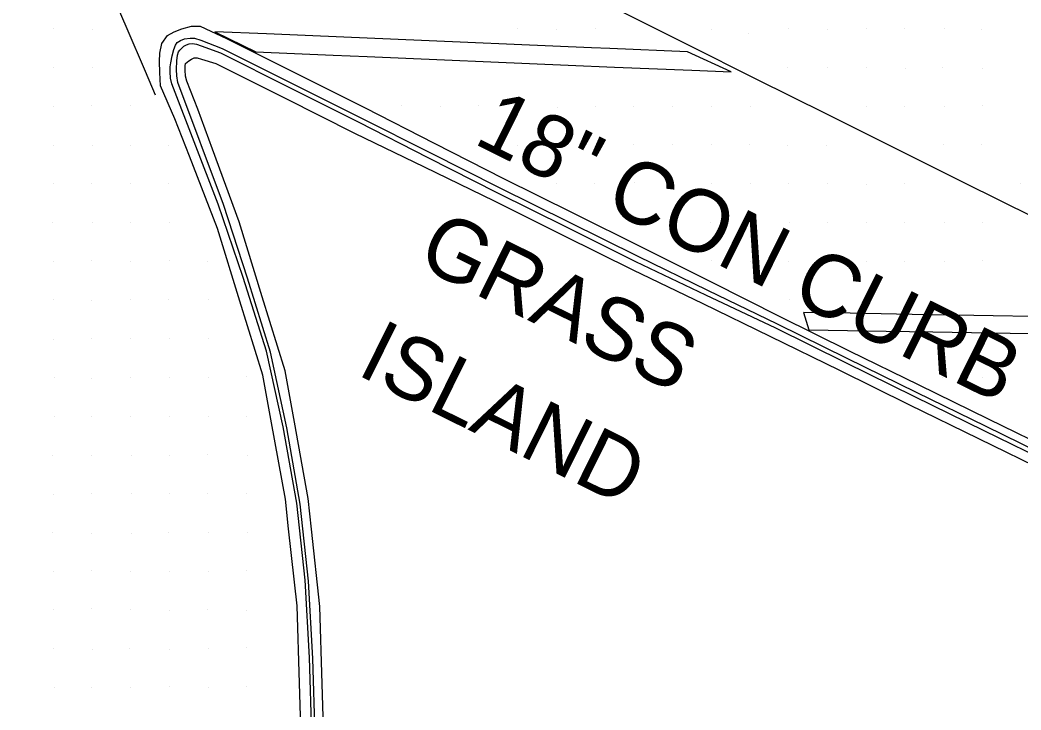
# Model space of a CAD drawing. Extents: x 2244337 to 2251208, y 199469 to 202984.
# Drawn here: x 2245411.9 to 2245476.6, y 202253.8 to 202298.3 of the extents above; entities that cross this region are included whole.
import ezdxf

# ---------------------------------------------------------------- set-up
doc = ezdxf.new("R2010")
doc.units = 0
for name, color, linetype in [('Exist DTM Breakline', 7, 'Continuous'), ('Exist DTM Scan Elevation Point', 7, 'Continuous'), ('Exist Roads Curb Topo', 7, 'Continuous'), ('Exist Roads EOP', 7, 'Continuous'), ('Exist Roads EOT', 7, 'Continuous'), ('Exist Roads Text', 7, 'Continuous')]:
    doc.layers.add(name, color=color, linetype=linetype)

msp = doc.modelspace()

# ---------------------------------------------------------------- linework, layer by layer
at = {"layer": 'Exist DTM Breakline'}
for points in [[(2245421.728, 202294.165), (2245421.649, 202294.516), (2245421.623, 202294.938), (2245421.626, 202295.267), (2245421.676, 202295.52), (2245421.754, 202295.964), (2245421.872, 202296.377), (2245421.979, 202296.66), (2245422.085, 202296.824), (2245422.287, 202296.96), (2245422.548, 202297.058), (2245422.924, 202297.116), (2245423.205, 202297.103), (2245423.604, 202296.989), (2245424.994, 202296.443)], [(2245422.127, 202294.238), (2245422.058, 202294.669), (2245422.047, 202295.084), (2245422.069, 202295.635), (2245422.11, 202296), (2245422.174, 202296.217), (2245422.248, 202296.34), (2245422.376, 202296.465), (2245422.51, 202296.589), (2245422.674, 202296.667), (2245422.85, 202296.749), (2245423.074, 202296.772), (2245423.319, 202296.714), (2245423.62, 202296.602), (2245424.877, 202296.167)], [(2245424.994, 202296.443), (2245429.463, 202294.2), (2245433.932, 202291.957), (2245438.403, 202289.719), (2245442.874, 202287.481), (2245447.351, 202285.256), (2245451.828, 202283.031), (2245456.329, 202280.853), (2245460.829, 202278.675), (2245465.316, 202276.468), (2245469.803, 202274.262), (2245474.295, 202272.066), (2245478.787, 202269.871), (2245483.279, 202267.675), (2245487.771, 202265.479), (2245492.268, 202263.293), (2245496.736, 202261.052)], [(2245424.877, 202296.167), (2245429.345, 202293.924), (2245433.814, 202291.681), (2245438.272, 202289.417), (2245442.729, 202287.151), (2245447.206, 202284.926), (2245451.684, 202282.701), (2245456.199, 202280.553), (2245460.714, 202278.405), (2245465.2, 202276.198), (2245469.687, 202273.992), (2245474.179, 202271.797), (2245478.671, 202269.601), (2245483.163, 202267.405), (2245487.655, 202265.21), (2245492.152, 202263.024), (2245496.609, 202260.761)], [(2245413.27, 202190.149), (2245415.285, 202194.715), (2245417.292, 202199.295), (2245419.282, 202203.882), (2245421.147, 202208.521), (2245422.955, 202213.181), (2245424.545, 202217.921), (2245426.136, 202222.662), (2245427.525, 202227.462), (2245428.788, 202232.3), (2245429.717, 202237.206), (2245430.317, 202242.165), (2245430.618, 202247.156), (2245430.769, 202252.15), (2245430.622, 202257.147), (2245430.343, 202262.136), (2245429.801, 202267.106), (2245428.927, 202272.028), (2245427.849, 202276.902), (2245426.337, 202281.667), (2245424.738, 202286.402), (2245421.728, 202294.165)], [(2245413.503, 202190.068), (2245415.489, 202194.652), (2245417.496, 202199.232), (2245419.484, 202203.819), (2245421.34, 202208.462), (2245423.142, 202213.125), (2245424.736, 202217.864), (2245426.331, 202222.602), (2245427.722, 202227.402), (2245428.985, 202232.24), (2245429.916, 202237.146), (2245430.523, 202242.105), (2245430.833, 202247.095), (2245430.993, 202252.088), (2245430.842, 202257.086), (2245430.565, 202262.074), (2245430.024, 202267.045), (2245429.156, 202271.968), (2245428.102, 202276.848), (2245426.627, 202281.625), (2245425.062, 202286.371), (2245422.127, 202294.238)]]:
    msp.add_lwpolyline(points, dxfattribs=at)
at = {"layer": 'Exist DTM Scan Elevation Point'}
for p, q in [((2245444.056, 202297.725), (2245444.056, 202297.725)), ((2245466.612, 202297.737), (2245466.612, 202297.737)), ((2245469.072, 202297.73), (2245469.072, 202297.73)), ((2245471.605, 202297.742), (2245471.605, 202297.742)), ((2245414.086, 202297.71), (2245414.086, 202297.71)), ((2245416.589, 202297.697), (2245416.589, 202297.697)), ((2245446.567, 202297.687), (2245446.567, 202297.687)), ((2245449.101, 202297.71), (2245449.101, 202297.71)), ((2245456.585, 202297.688), (2245456.585, 202297.688)), ((2245458.97, 202297.431), (2245458.97, 202297.431)), ((2245461.563, 202297.707), (2245461.563, 202297.707)), ((2245464.086, 202297.692), (2245464.086, 202297.692)), ((2245474.046, 202297.684), (2245474.046, 202297.684)), ((2245414.102, 202295.2), (2245414.102, 202295.2)), ((2245416.587, 202295.184), (2245416.587, 202295.184)), ((2245461.497, 202295.203), (2245461.497, 202295.203)), ((2245464.084, 202295.231), (2245464.084, 202295.231)), ((2245466.575, 202295.232), (2245466.575, 202295.232)), ((2245469.097, 202295.142), (2245469.097, 202295.142)), ((2245471.508, 202295.215), (2245471.508, 202295.215)), ((2245474.087, 202295.172), (2245474.087, 202295.172)), ((2245414.102, 202292.706), (2245414.102, 202292.706)), ((2245416.539, 202292.74), (2245416.539, 202292.74)), ((2245419.046, 202292.752), (2245419.046, 202292.752)), ((2245436.566, 202292.731), (2245436.566, 202292.731)), ((2245439.061, 202292.713), (2245439.061, 202292.713)), ((2245441.569, 202292.732), (2245441.569, 202292.732)), ((2245444.079, 202292.701), (2245444.079, 202292.701)), ((2245446.612, 202292.66), (2245446.612, 202292.66)), ((2245449.072, 202292.672), (2245449.072, 202292.672)), ((2245451.578, 202292.692), (2245451.578, 202292.692)), ((2245454.047, 202292.686), (2245454.047, 202292.686)), ((2245456.591, 202292.683), (2245456.591, 202292.683)), ((2245459.089, 202292.709), (2245459.089, 202292.709)), ((2245466.574, 202292.725), (2245466.574, 202292.725)), ((2245469.061, 202292.722), (2245469.061, 202292.722)), ((2245471.625, 202292.718), (2245471.625, 202292.718)), ((2245474.063, 202292.731), (2245474.063, 202292.731)), ((2245414.063, 202290.21), (2245414.063, 202290.21)), ((2245416.597, 202290.201), (2245416.597, 202290.201)), ((2245419.07, 202290.187), (2245419.07, 202290.187)), ((2245421.53, 202290.182), (2245421.53, 202290.182)), ((2245441.54, 202290.187), (2245441.54, 202290.187)), ((2245444.038, 202290.191), (2245444.038, 202290.191)), ((2245446.63, 202290.198), (2245446.63, 202290.198)), ((2245449.094, 202290.189), (2245449.094, 202290.189)), ((2245451.55, 202290.219), (2245451.55, 202290.219)), ((2245454.046, 202290.219), (2245454.046, 202290.219)), ((2245456.605, 202290.214), (2245456.605, 202290.214)), ((2245459.052, 202290.216), (2245459.052, 202290.216)), ((2245461.512, 202290.177), (2245461.512, 202290.177)), ((2245464.041, 202290.194), (2245464.041, 202290.194)), ((2245471.573, 202290.229), (2245471.573, 202290.229)), ((2245474.02, 202290.221), (2245474.02, 202290.221)), ((2245414.087, 202287.718), (2245414.087, 202287.718)), ((2245416.557, 202287.713), (2245416.557, 202287.713)), ((2245419.036, 202287.72), (2245419.036, 202287.72)), ((2245421.53, 202287.718), (2245421.53, 202287.718)), ((2245446.587, 202287.725), (2245446.587, 202287.725)), ((2245449.016, 202287.722), (2245449.016, 202287.722)), ((2245451.598, 202287.767), (2245451.598, 202287.767)), ((2245454.034, 202287.7), (2245454.034, 202287.7)), ((2245456.556, 202287.723), (2245456.556, 202287.723)), ((2245459.084, 202287.704), (2245459.084, 202287.704)), ((2245461.556, 202287.718), (2245461.556, 202287.718)), ((2245464.08, 202287.721), (2245464.08, 202287.721)), ((2245466.564, 202287.693), (2245466.564, 202287.693)), ((2245469.059, 202287.711), (2245469.059, 202287.711)), ((2245476.553, 202287.719), (2245476.553, 202287.719)), ((2245414.048, 202285.185), (2245414.048, 202285.185)), ((2245416.588, 202285.211), (2245416.588, 202285.211)), ((2245419.086, 202285.205), (2245419.086, 202285.205)), ((2245421.574, 202285.223), (2245421.574, 202285.223)), ((2245451.551, 202285.22), (2245451.551, 202285.22)), ((2245454.105, 202285.22), (2245454.105, 202285.22)), ((2245456.525, 202285.227), (2245456.525, 202285.227)), ((2245459.13, 202285.216), (2245459.13, 202285.216)), ((2245461.599, 202285.203), (2245461.599, 202285.203)), ((2245464.072, 202285.22), (2245464.072, 202285.22)), ((2245466.565, 202285.207), (2245466.565, 202285.207)), ((2245469.06, 202285.187), (2245469.06, 202285.187)), ((2245471.61, 202285.201), (2245471.61, 202285.201)), ((2245474.084, 202285.222), (2245474.084, 202285.222)), ((2245414.064, 202282.725), (2245414.064, 202282.725)), ((2245416.543, 202282.764), (2245416.543, 202282.764)), ((2245419.088, 202282.706), (2245419.088, 202282.706)), ((2245421.567, 202282.73), (2245421.567, 202282.73)), ((2245424.062, 202282.666), (2245424.062, 202282.666)), ((2245456.587, 202282.768), (2245456.587, 202282.768)), ((2245459.088, 202282.669), (2245459.088, 202282.669)), ((2245461.588, 202282.705), (2245461.588, 202282.705)), ((2245464.074, 202282.712), (2245464.074, 202282.712)), ((2245466.571, 202282.701), (2245466.571, 202282.701)), ((2245469.066, 202282.681), (2245469.066, 202282.681)), ((2245471.6, 202282.724), (2245471.6, 202282.724)), ((2245474.098, 202282.739), (2245474.098, 202282.739)), ((2245414.087, 202280.24), (2245414.087, 202280.24)), ((2245416.567, 202280.186), (2245416.567, 202280.186)), ((2245419.063, 202280.227), (2245419.063, 202280.227)), ((2245421.527, 202280.223), (2245421.527, 202280.223)), ((2245424.105, 202280.217), (2245424.105, 202280.217)), ((2245461.608, 202280.227), (2245461.608, 202280.227)), ((2245414.067, 202277.684), (2245414.067, 202277.684)), ((2245416.547, 202277.702), (2245416.547, 202277.702)), ((2245419.075, 202277.697), (2245419.075, 202277.697)), ((2245421.584, 202277.708), (2245421.584, 202277.708)), ((2245424.091, 202277.733), (2245424.091, 202277.733)), ((2245414.138, 202275.21), (2245414.138, 202275.21)), ((2245416.562, 202275.169), (2245416.562, 202275.169)), ((2245419.078, 202275.218), (2245419.078, 202275.218)), ((2245421.567, 202275.181), (2245421.567, 202275.181)), ((2245424.101, 202275.218), (2245424.101, 202275.218)), ((2245426.578, 202275.266), (2245426.578, 202275.266)), ((2245471.515, 202275.221), (2245471.515, 202275.221)), ((2245474.103, 202275.223), (2245474.103, 202275.223)), ((2245414.141, 202272.722), (2245414.141, 202272.722)), ((2245416.56, 202272.718), (2245416.56, 202272.718)), ((2245419.042, 202272.706), (2245419.042, 202272.706)), ((2245421.56, 202272.687), (2245421.56, 202272.687)), ((2245424.092, 202272.716), (2245424.092, 202272.716)), ((2245426.553, 202272.704), (2245426.553, 202272.704)), ((2245414.05, 202270.199), (2245414.05, 202270.199)), ((2245416.567, 202270.205), (2245416.567, 202270.205)), ((2245419.115, 202270.187), (2245419.115, 202270.187)), ((2245421.567, 202270.199), (2245421.567, 202270.199)), ((2245424.068, 202270.247), (2245424.068, 202270.247)), ((2245426.622, 202270.207), (2245426.622, 202270.207)), ((2245414.073, 202267.674), (2245414.073, 202267.674)), ((2245416.577, 202267.714), (2245416.577, 202267.714)), ((2245419.116, 202267.694), (2245419.116, 202267.694)), ((2245421.6, 202267.72), (2245421.6, 202267.72)), ((2245424.014, 202267.718), (2245424.014, 202267.718)), ((2245426.583, 202267.726), (2245426.583, 202267.726)), ((2245414.035, 202265.18), (2245414.035, 202265.18)), ((2245416.556, 202265.169), (2245416.556, 202265.169)), ((2245419.101, 202265.175), (2245419.101, 202265.175)), ((2245421.551, 202265.183), (2245421.551, 202265.183)), ((2245424.082, 202265.215), (2245424.082, 202265.215)), ((2245426.593, 202265.236), (2245426.593, 202265.236)), ((2245414.081, 202262.717), (2245414.081, 202262.717)), ((2245416.552, 202262.733), (2245416.552, 202262.733)), ((2245419.058, 202262.666), (2245419.058, 202262.666)), ((2245421.584, 202262.705), (2245421.584, 202262.705)), ((2245424.072, 202262.678), (2245424.072, 202262.678)), ((2245426.57, 202262.76), (2245426.57, 202262.76)), ((2245414.074, 202260.242), (2245414.074, 202260.242)), ((2245416.548, 202260.288), (2245416.548, 202260.288)), ((2245419.049, 202260.241), (2245419.049, 202260.241)), ((2245421.587, 202260.188), (2245421.587, 202260.188)), ((2245424.07, 202260.208), (2245424.07, 202260.208)), ((2245426.551, 202260.199), (2245426.551, 202260.199)), ((2245414.084, 202257.708), (2245414.084, 202257.708)), ((2245416.593, 202257.671), (2245416.593, 202257.671)), ((2245419.034, 202257.698), (2245419.034, 202257.698)), ((2245421.595, 202257.682), (2245421.595, 202257.682)), ((2245424.087, 202257.695), (2245424.087, 202257.695)), ((2245426.573, 202257.773), (2245426.573, 202257.773)), ((2245414.129, 202255.232), (2245414.129, 202255.232)), ((2245416.562, 202255.199), (2245416.562, 202255.199)), ((2245419.071, 202255.215), (2245419.071, 202255.215)), ((2245421.575, 202255.243), (2245421.575, 202255.243)), ((2245424.088, 202255.202), (2245424.088, 202255.202)), ((2245426.557, 202255.265), (2245426.557, 202255.265))]:
    msp.add_line(p, q, dxfattribs=at)
at = {"layer": 'Exist Roads Curb Topo'}
for points in [[(2245422.695, 202294.342), (2245422.626, 202294.663), (2245422.587, 202295.053), (2245422.587, 202295.315), (2245422.626, 202295.475), (2245422.825, 202295.654), (2245422.997, 202295.753), (2245423.187, 202295.831), (2245423.365, 202295.846), (2245423.655, 202295.761), (2245424.579, 202295.468)], [(2245424.579, 202295.468), (2245429.047, 202293.225), (2245433.533, 202290.974), (2245438.033, 202288.794), (2245442.543, 202286.608), (2245447.02, 202284.383), (2245451.513, 202282.151), (2245456.016, 202279.978), (2245460.36, 202277.883), (2245464.847, 202275.676), (2245469.334, 202273.47), (2245473.826, 202271.274), (2245478.318, 202269.079), (2245482.81, 202266.883), (2245487.303, 202264.687), (2245491.8, 202262.501), (2245494.79, 202261.047), (2245496.619, 202260.045)], [(2245431.595, 202250.441), (2245431.445, 202255.438), (2245431.294, 202260.443), (2245430.756, 202265.414), (2245430.539, 202267.411), (2245429.65, 202272.331), (2245429.054, 202275.631), (2245427.58, 202280.409), (2245426.084, 202285.259), (2245424.356, 202289.951), (2245423.409, 202292.524), (2245422.695, 202294.342)]]:
    msp.add_lwpolyline(points, dxfattribs=at)
at = {"layer": 'Exist Roads EOP'}
for points in [[(2245420.998, 202294.031), (2245420.958, 202294.884), (2245420.937, 202295.593), (2245420.963, 202296.142), (2245421.093, 202296.763), (2245421.467, 202297.27), (2245421.877, 202297.512), (2245422.381, 202297.708), (2245423, 202297.891), (2245423.566, 202297.873)], [(2245423.566, 202297.873), (2245425.273, 202297.096), (2245429.742, 202294.853), (2245434.228, 202292.602), (2245438.685, 202290.337), (2245443.163, 202288.061), (2245447.64, 202285.837), (2245452.133, 202283.604), (2245456.599, 202281.355), (2245460.989, 202279.144), (2245465.476, 202276.938), (2245469.963, 202274.731), (2245474.455, 202272.536), (2245478.947, 202270.34), (2245483.439, 202268.144), (2245487.932, 202265.948), (2245492.429, 202263.762), (2245495.419, 202262.309), (2245497.541, 202261.192)], [(2245430.124, 202250.494), (2245429.973, 202255.491), (2245429.822, 202260.485), (2245429.277, 202265.455), (2245429.067, 202267.364), (2245428.169, 202272.282), (2245427.607, 202275.355), (2245426.129, 202280.131), (2245424.678, 202284.822), (2245422.875, 202289.485), (2245421.94, 202291.905), (2245420.998, 202294.031)]]:
    msp.add_lwpolyline(points, dxfattribs=at)
at = {"layer": 'Exist Roads EOT'}
for points in [[(2245395.506, 202325.864), (2245399.696, 202323.136), (2245401.363, 202322.05), (2245404.139, 202319.833), (2245406.103, 202318.001), (2245408.962, 202314.903), (2245410.92, 202312.438), (2245412.785, 202309.535), (2245414.435, 202306.902), (2245416.776, 202302.484), (2245416.855, 202302.334), (2245418.824, 202297.738), (2245420.005, 202294.98), (2245420.659, 202293.453)], [(2245477.423, 202285.526), (2245472.947, 202287.756), (2245468.472, 202289.986), (2245463.997, 202292.215), (2245459.522, 202294.445), (2245455.047, 202296.675), (2245450.571, 202298.905), (2245446.096, 202301.135), (2245441.621, 202303.365), (2245437.146, 202305.595), (2245432.671, 202307.825), (2245428.196, 202310.055), (2245423.72, 202312.285), (2245419.245, 202314.515), (2245414.77, 202316.745), (2245410.295, 202318.975)], [(2245432.849, 202297.169), (2245427.855, 202297.381), (2245424.515, 202297.523), (2245427.157, 202296.221), (2245432.152, 202296.011), (2245434.342, 202295.918), (2245439.337, 202295.707), (2245442.334, 202295.581), (2245447.33, 202295.37), (2245450.327, 202295.244), (2245455.323, 202295.033), (2245457.85, 202294.926), (2245455.026, 202296.226), (2245450.03, 202296.439), (2245448.834, 202296.49), (2245443.839, 202296.702), (2245440.842, 202296.829), (2245435.846, 202297.042), (2245432.849, 202297.169)], [(2245489.84, 202278.911), (2245486.531, 202278.972), (2245481.532, 202279.062), (2245478.532, 202279.117), (2245473.533, 202279.208), (2245470.533, 202279.262), (2245465.534, 202279.353), (2245462.535, 202279.408), (2245462.874, 202278.291), (2245467.873, 202278.207), (2245470.873, 202278.156), (2245475.872, 202278.072), (2245478.871, 202278.021), (2245483.871, 202277.937), (2245486.87, 202277.887), (2245491.869, 202277.802), (2245492.266, 202277.796), (2245489.84, 202278.911)]]:
    msp.add_lwpolyline(points, dxfattribs=at)

# ---------------------------------------------------------------- texts
at = {"layer": 'Exist Roads Text'}
for s, rotation, p in [('18" CON CURB', 333.64718, (2245441.134, 202290.352)), ('GRASS ', 333.65751, (2245437.431, 202282.511)), ('ISLAND', 333.65751, (2245433.587, 202275.443))]:
    msp.add_text(s, height=4.02, rotation=rotation, dxfattribs=at).set_placement(p)

doc.saveas('drawing.dxf')
